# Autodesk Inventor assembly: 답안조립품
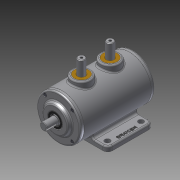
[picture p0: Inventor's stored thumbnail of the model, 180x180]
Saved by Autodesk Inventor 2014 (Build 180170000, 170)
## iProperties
Created: 2014-12
Part Number: 답안조립품
Document SubType Name: Assembly
Designer: Owner
Author: Owner
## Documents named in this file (10)
- C:\Users\Owner\Desktop\441223V1001\답안조립품.iam
- C:\Users\Owner\Desktop\441223V1001\본체.ipt
- C:\Users\Owner\Desktop\441223V1001\M4-소켓머리.ipt
- C:\Users\Owner\Desktop\441223V1001\뒷커버.ipt
- C:\Users\Owner\Desktop\441223V1001\베어링 6203.ipt
- C:\Users\Owner\Desktop\441223V1001\부시.ipt
- C:\Users\Owner\Desktop\441223V1001\슬라이더.ipt
- C:\Users\Owner\Desktop\441223V1001\앞커버.ipt
- C:\Users\Owner\Desktop\441223V1001\오일실.ipt
- C:\Users\Owner\Desktop\441223V1001\축.ipt
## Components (11 placed, 3 different names)
1. 7-베어링 6203:1
2. 8-오일실:1
3. 7-베어링 6203:2
4. 9-M4-소켓머리:1
5. 9-M4-소켓머리:3
6. 9-M4-소켓머리:4
7. 9-M4-소켓머리:5
8. 9-M4-소켓머리:2
9. 9-M4-소켓머리:6
10. 9-M4-소켓머리:7
11. 9-M4-소켓머리:8
